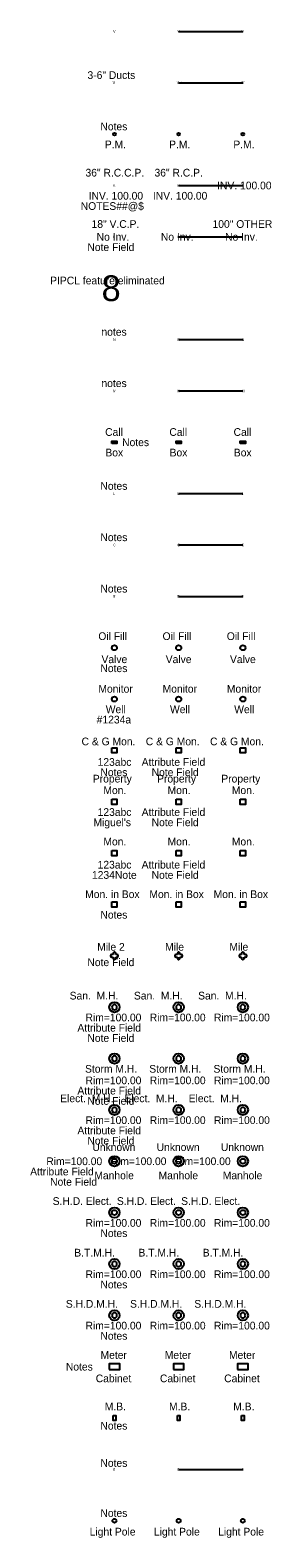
# Model space of a CAD drawing. Extents: x 40011 to 50684, y 49949 to 72236.
# Drawn here: x 49967 to 50061, y 51773 to 52360 of the extents above; entities that cross this region are included whole.
import ezdxf

# ---------------------------------------------------------------- set-up
doc = ezdxf.new("R2010")
doc.units = 0
for name, color, linetype in [('10', 7, 'Continuous'), ('12', 7, 'Continuous'), ('13', 7, 'Continuous'), ('15', 7, 'Continuous'), ('16', 7, 'Continuous'), ('17', 7, 'Continuous'), ('2', 7, 'Continuous'), ('20', 7, 'Continuous'), ('41', 7, 'Continuous'), ('44', 7, 'Continuous'), ('49', 7, 'Continuous'), ('5', 7, 'Continuous'), ('50', 7, 'Continuous'), ('56', 7, 'Continuous'), ('9', 7, 'Continuous')]:
    doc.layers.add(name, color=color, linetype=linetype)

msp = doc.modelspace()

# ---------------------------------------------------------------- linework, layer by layer
at = {"layer": '10'}
for points in [[(50025, 52300), (50050, 52300)], [(50025, 52280), (50050, 52280)]]:
    msp.add_lwpolyline(points, dxfattribs=at)
at = {"layer": '12'}
msp.add_lwpolyline([(50025, 52360), (50050, 52360)], dxfattribs=at)
for centre, radius in [((50000, 51940), 2), ((50025, 51940), 2), ((50050, 51940), 2), ((50000, 51900), 2), ((50000, 51900), 1), ((50025, 51900), 2), ((50025, 51900), 1), ((50050, 51900), 2), ((50050, 51900), 1)]:
    msp.add_circle(centre, radius, dxfattribs=at)
for centre, start, end in [((50000, 51940), 0, 180), ((50000, 51940), 180, 0), ((50025, 51940), 0, 180), ((50025, 51940), 180, 0), ((50050, 51940), 0, 180), ((50050, 51940), 180, 0)]:
    msp.add_arc(centre, 1, start, end, dxfattribs=at)
at = {"layer": '13'}
for centre in [(50000, 51880), (50025, 51880), (50050, 51880)]:
    msp.add_circle(centre, 2, dxfattribs=at)
for centre, start, end in [((50000, 51880), 0, 180), ((50025, 51880), 0, 180), ((50050, 51880), 0, 180), ((50000, 51880), 180, 0), ((50025, 51880), 180, 0), ((50050, 51880), 180, 0)]:
    msp.add_arc(centre, 1, start, end, dxfattribs=at)
at = {"layer": '15'}
for centre in [(50000, 52100), (50025, 52100), (50050, 52100)]:
    msp.add_circle(centre, 1, dxfattribs=at)
at = {"layer": '16'}
for centre in [(50000, 51980), (50025, 51980), (50050, 51980)]:
    msp.add_circle(centre, 2, dxfattribs=at)
for centre, start, end in [((50000, 51980), 0, 180), ((50025, 51980), 0, 180), ((50050, 51980), 0, 180), ((50000, 51980), 180, 0), ((50025, 51980), 180, 0), ((50050, 51980), 180, 0)]:
    msp.add_arc(centre, 1, start, end, dxfattribs=at)
at = {"layer": '17'}
msp.add_lwpolyline([(50025, 52340), (50050, 52340)], dxfattribs=at)
at = {"layer": '2'}
for points in [[(50025, 52240), (50050, 52240)], [(50025, 52220), (50050, 52220)], [(50025, 52180), (50050, 52180)]]:
    msp.add_lwpolyline(points, dxfattribs=at)
at = {"layer": '20'}
for points in [[(49997.95, 51838.95), (50002.05, 51838.95), (50002.05, 51841.05), (49997.95, 51841.05)], [(50022.95, 51838.95), (50027.05, 51838.95), (50027.05, 51841.05), (50022.95, 51841.05)], [(50047.95, 51838.95), (50052.05, 51838.95), (50052.05, 51841.05), (50047.95, 51841.05)]]:
    msp.add_lwpolyline(points, close=True, dxfattribs=at)
at = {"layer": '5'}
for p, q in [((49999.5, 52000.5), (49999, 52000.5)), ((49999, 51999.5), (49999.5, 51999.5)), ((49999.5, 52001), (49999.5, 52000.5)), ((49999.5, 51999.5), (49999.5, 51999)), ((50000.5, 52000.5), (50000.5, 52001)), ((50001, 52000.5), (50000.5, 52000.5)), ((50000.5, 51999), (50000.5, 51999.5)), ((50000.5, 51999.5), (50001, 51999.5)), ((50024.5, 52000.5), (50024, 52000.5)), ((50024, 51999.5), (50024.5, 51999.5)), ((50024.5, 52001), (50024.5, 52000.5)), ((50024.5, 51999.5), (50024.5, 51999)), ((50025.5, 52000.5), (50025.5, 52001)), ((50026, 52000.5), (50025.5, 52000.5)), ((50025.5, 51999), (50025.5, 51999.5)), ((50025.5, 51999.5), (50026, 51999.5)), ((50049.5, 52000.5), (50049, 52000.5)), ((50049, 51999.5), (50049.5, 51999.5)), ((50049.5, 52001), (50049.5, 52000.5)), ((50049.5, 51999.5), (50049.5, 51999)), ((50050.5, 52000.5), (50050.5, 52001)), ((50051, 52000.5), (50050.5, 52000.5)), ((50050.5, 51999), (50050.5, 51999.5)), ((50050.5, 51999.5), (50051, 51999.5))]:
    msp.add_line(p, q, dxfattribs=at)
for points in [[(49999, 52199.5), (49999, 52200.5), (50001, 52200.5), (50001, 52199.5)], [(50024, 52199.5), (50024, 52200.5), (50026, 52200.5), (50026, 52199.5)], [(50049, 52199.5), (50049, 52200.5), (50051, 52200.5), (50051, 52199.5)], [(49999, 52081), (50001, 52081), (50001, 52079), (49999, 52079)], [(50024, 52081), (50026, 52081), (50026, 52079), (50024, 52079)], [(50049, 52081), (50051, 52081), (50051, 52079), (50049, 52079)], [(49999, 52061), (50001, 52061), (50001, 52059), (49999, 52059)], [(50024, 52061), (50026, 52061), (50026, 52059), (50024, 52059)], [(50049, 52061), (50051, 52061), (50051, 52059), (50049, 52059)], [(49999, 52041), (50001, 52041), (50001, 52039), (49999, 52039)], [(50024, 52041), (50026, 52041), (50026, 52039), (50024, 52039)], [(50049, 52041), (50051, 52041), (50051, 52039), (50049, 52039)], [(49999, 52021), (50001, 52021), (50001, 52019), (49999, 52019)], [(50024, 52021), (50026, 52021), (50026, 52019), (50024, 52019)], [(50049, 52021), (50051, 52021), (50051, 52019), (50049, 52019)], [(49999.5, 51821), (50000.5, 51821), (50000.5, 51819), (49999.5, 51819)], [(50024.5, 51821), (50025.5, 51821), (50025.5, 51819), (50024.5, 51819)], [(50049.5, 51821), (50050.5, 51821), (50050.5, 51819), (50049.5, 51819)]]:
    msp.add_lwpolyline(points, close=True, dxfattribs=at)
for points in [[(50025, 52160), (50050, 52160)], [(50025, 52140), (50050, 52140)], [(50025, 51800), (50050, 51800)]]:
    msp.add_lwpolyline(points, dxfattribs=at)
for centre, radius in [((50000, 52320), 0.5), ((50025, 52320), 0.5), ((50050, 52320), 0.5), ((50000, 52120), 1), ((50025, 52120), 1), ((50050, 52120), 1), ((50000, 51780), 0.75), ((50025, 51780), 0.75), ((50050, 51780), 0.75)]:
    msp.add_circle(centre, radius, dxfattribs=at)
for centre, start, end in [((49999, 52000), 90, 270), ((50000, 52001), 0, 180), ((50000, 51999), 180, 0), ((50001, 52000), 270, 90), ((50024, 52000), 90, 270), ((50025, 52001), 0, 180), ((50025, 51999), 180, 0), ((50026, 52000), 270, 90), ((50049, 52000), 90, 270), ((50050, 52001), 0, 180), ((50050, 51999), 180, 0), ((50051, 52000), 270, 90)]:
    msp.add_arc(centre, 0.5, start, end, dxfattribs=at)
at = {"layer": '56'}
for centre, radius in [((50000, 51920), 2), ((50000, 51920), 1), ((50025, 51920), 2), ((50025, 51920), 1), ((50050, 51920), 2), ((50050, 51920), 1)]:
    msp.add_circle(centre, radius, dxfattribs=at)
at = {"layer": '9'}
for centre in [(50000, 51960), (50025, 51960), (50050, 51960), (50000, 51860), (50025, 51860), (50050, 51860)]:
    msp.add_circle(centre, 2, dxfattribs=at)
for centre, start, end in [((50000, 51960), 0, 180), ((50000, 51960), 180, 0), ((50025, 51960), 0, 180), ((50025, 51960), 180, 0), ((50050, 51960), 0, 180), ((50050, 51960), 180, 0), ((50000, 51860), 0, 180), ((50000, 51860), 180, 0), ((50025, 51860), 0, 180), ((50025, 51860), 180, 0), ((50050, 51860), 0, 180), ((50050, 51860), 180, 0)]:
    msp.add_arc(centre, 1, start, end, dxfattribs=at)

# ---------------------------------------------------------------- texts
at = {"layer": '12'}
for s, p in [('Elect.  M.H.', (49978.9, 51943)), ('Elect.  M.H.', (50003.9, 51943)), ('Elect.  M.H.', (50028.9, 51943)), ('S.H.D. Elect.', (49975.96, 51903)), ('S.H.D. Elect.', (50000.96, 51903)), ('S.H.D. Elect.', (50025.96, 51903))]:
    msp.add_text(s, height=3, dxfattribs=at).set_placement(p)
at = {"layer": '13'}
for p in [(49984.37, 51882.9), (50009.37, 51882.9), (50034.37, 51882.9)]:
    msp.add_text('B.T.M.H.', height=3, dxfattribs=at).set_placement(p)
at = {"layer": '15'}
for s, p in [('Monitor', (49993.76, 52102.5)), ('Monitor', (50018.76, 52102.5)), ('Monitor', (50043.76, 52102.5)), ('Well', (49996.63, 52094.5)), ('Well', (50021.63, 52094.5)), ('Well', (50046.63, 52094.5))]:
    msp.add_text(s, height=3, dxfattribs=at).set_placement(p)
at = {"layer": '16'}
for p in [(49982.58, 51983), (50007.58, 51983), (50032.58, 51983)]:
    msp.add_text('San.  M.H.', height=3, dxfattribs=at).set_placement(p)
at = {"layer": '20'}
for s, p in [('Meter', (49994.59, 51843.05)), ('Meter', (50019.59, 51843.05)), ('Meter', (50044.59, 51843.05)), ('Cabinet', (49992.72, 51833.95)), ('Cabinet', (50017.72, 51833.95)), ('Cabinet', (50042.72, 51833.95))]:
    msp.add_text(s, height=3, dxfattribs=at).set_placement(p)
at = {"layer": '41'}
for s, p in [('3-6" Ducts', (49989.51, 52341.5)), ('Notes', (49994.55, 52321.5)), ('36" R.C.C.P.', (49988.74, 52303.5)), ('NOTES##@$', (49986.89, 52290.5)), ('INV. 100.00', (49989.97, 52294.5)), ('18" V.C.P.', (49991.1, 52283.5)), ('100" OTHER', (50038.18, 52283.5)), ('No Inv.', (49993.08, 52278.5)), ('No Inv.', (50018.08, 52278.5)), ('No Inv.', (50043.08, 52278.5)), ('Note Field', (49989.48, 52274.5)), ('notes', (49994.95, 52241.5)), ('notes', (49994.95, 52221.5)), ('Notes', (50003, 52198.5)), ('Notes', (49994.55, 52181.5)), ('Notes', (49994.55, 52161.5)), ('Notes', (49994.55, 52141.5)), ('Notes', (49994.55, 52110.5)), ('#1234a', (49993.1, 52090.5)), ('Notes', (49994.55, 52070)), ('Note Field', (50014.48, 52070)), ('123abc', (49993.46, 52054.5)), ('Attribute Field', (50010.6, 52054.5)), ("Miguel's", (49991.85, 52050.5)), ('Note Field', (50014.48, 52050.5)), ('1234Note', (49991.26, 52030)), ('Note Field', (50014.48, 52030)), ('Mon. in Box', (49988.61, 52022.5)), ('Mon. in Box', (50013.61, 52022.5)), ('Mon. in Box', (50038.61, 52022.5)), ('Notes', (49994.55, 52014.5)), (' Mile 2', (49992.19, 52002)), (' Mile ', (50018.62, 52002)), (' Mile ', (50043.62, 52002)), ('Note Field', (49989.48, 51996)), ('Rim=100.00', (49988.75, 51974.5)), ('Rim=100.00', (50013.75, 51974.5)), ('Rim=100.00', (50038.75, 51974.5)), ('Attribute Field', (49985.6, 51970.5)), ('Note Field', (49989.48, 51966.5)), ('Storm M.H.', (49988.56, 51954.5)), ('Storm M.H.', (50013.56, 51954.5)), ('Storm M.H.', (50038.56, 51954.5)), ('Rim=100.00', (49988.75, 51950)), ('Rim=100.00', (50013.75, 51950)), ('Rim=100.00', (50038.75, 51950)), ('Attribute Field', (49985.6, 51946)), ('Note Field', (49989.48, 51942)), ('Rim=100.00', (49988.75, 51934.5)), ('Rim=100.00', (50013.75, 51934.5)), ('Rim=100.00', (50038.75, 51934.5)), ('Attribute Field', (49985.6, 51930.5)), ('Note Field', (49989.48, 51926.5)), ('Attribute Field', (49967.2, 51914.5)), ('Rim=100.00', (49973.5, 51918.5)), ('Rim=100.00', (49998.5, 51918.5)), ('Rim=100.00', (50023.5, 51918.5)), ('Note Field', (49974.97, 51910.5)), ('Rim=100.00', (49988.75, 51894.5)), ('Notes', (49994.55, 51890.5)), ('Rim=100.00', (50013.75, 51894.5)), ('Rim=100.00', (50038.75, 51894.5)), ('Rim=100.00', (49988.75, 51874.5)), ('Rim=100.00', (50013.75, 51874.5)), ('Rim=100.00', (50038.75, 51874.5)), ('Notes', (49994.55, 51870.5)), ('Rim=100.00', (49988.75, 51854.5)), ('Rim=100.00', (50013.75, 51854.5)), ('Rim=100.00', (50038.75, 51854.5)), ('Notes', (49994.55, 51850.5)), ('Notes', (49981.1, 51838.5)), ('Notes', (49994.55, 51815.5)), ('Notes', (49994.55, 51801)), ('Notes', (49994.55, 51781.5))]:
    msp.add_text(s, height=3, dxfattribs=at).set_placement(p)
for s, p in [('36" R.C.P.', (50015.6, 52303.5)), ('INV. 100.00', (50039.97, 52298.5)), ('INV. 100.00', (50014.97, 52294.5))]:
    msp.add_text(s, height=3, rotation=360, dxfattribs=at).set_placement(p)
at = {"layer": '44'}
for s, height, p in [('Pav. Mark. CTV', 0.2, (49999.08, 52340.3)), ('Overhang', 0.2, (49999.39, 52140.3)), ('Landscape Tie', 0.1, (49999.52, 51800.15))]:
    msp.add_text(s, height=height, dxfattribs=at).set_placement(p)
for s, height, p in [('Pav. Mark. CTV', 0.2, (50024.08, 52340.3)), ('Pav. Mark. CTV', 0.2, (50049.08, 52340.3)), ('K', 1, (49999.5, 52299.5)), ('K', 1, (50024.5, 52299.5)), ('K', 1, (50049.5, 52299.5)), ('I', 1, (49999.5, 52279.5)), ('I', 1, (50024.5, 52279.5)), ('I', 1, (50049.5, 52279.5)), ('N', 1, (49999.5, 52239.5)), ('N', 1, (50024.5, 52239.5)), ('N', 1, (50049.5, 52239.5)), ('M', 1, (49999.5, 52219.5)), ('M', 1, (50024.5, 52219.5)), ('M', 1, (50049.5, 52219.5)), ('L', 1, (49999.5, 52179.5)), ('L', 1, (50024.5, 52179.5)), ('L', 1, (50049.5, 52179.5)), ('C', 1, (49999.5, 52159.5)), ('C', 1, (50024.5, 52159.5)), ('C', 1, (50049.5, 52159.5)), ('8', 1, (49999.5, 52139.5)), ('Overhang', 0.2, (50024.39, 52140.3)), ('8', 1, (50024.5, 52139.5)), ('Overhang', 0.2, (50049.39, 52140.3)), ('8', 1, (50049.5, 52139.5)), ('8', 1, (49999.5, 51799.5)), ('Landscape Tie', 0.1, (50024.52, 51800.15)), ('8', 1, (50024.5, 51799.5)), ('Landscape Tie', 0.1, (50049.52, 51800.15)), ('8', 1, (50049.5, 51799.5))]:
    msp.add_text(s, height=height, rotation=360, dxfattribs=at).set_placement(p)
at = {"layer": '49'}
for s, p in [('V', (49999.5, 52359.5)), ('V', (50024.5, 52359.5)), ('V', (50049.5, 52359.5)), ('8', (49999.5, 52339.5)), ('8', (50024.5, 52339.5)), ('8', (50049.5, 52339.5))]:
    msp.add_text(s, height=1, rotation=360, dxfattribs=at).set_placement(p)
at = {"layer": '5'}
for s, p in [('P.M.', (49996.28, 52314.5)), ('P.M.', (50021.28, 52314.5)), ('P.M.', (50046.28, 52314.5)), ('Call', (49996.38, 52202.5)), ('Call', (50021.38, 52202.5)), ('Call', (50046.38, 52202.5)), ('Box', (49996.48, 52194.5)), ('Box', (50021.48, 52194.5)), ('Box', (50046.48, 52194.5)), ('Oil Fill', (49993.74, 52123)), ('Oil Fill', (50018.74, 52123)), ('Oil Fill', (50043.74, 52123)), ('Valve', (49994.97, 52114)), ('Valve', (50019.97, 52114)), ('Valve', (50044.97, 52114)), ('C & G Mon.', (49987.21, 52082)), ('C & G Mon.', (50012.21, 52082)), ('C & G Mon.', (50037.21, 52082)), ('123abc', (49993.46, 52074)), ('Attribute Field', (50010.6, 52074)), ('Property', (49991.6, 52067.5)), ('Property', (50016.6, 52067.5)), ('Property', (50041.6, 52067.5)), ('Mon.', (49995.7, 52063)), ('Mon.', (50020.7, 52063)), ('Mon.', (50045.7, 52063)), ('123abc', (49993.46, 52034)), ('Attribute Field', (50010.6, 52034)), ('M.B.', (49996.25, 51823)), ('M.B.', (50021.25, 51823)), ('M.B.', (50046.25, 51823)), ('Light Pole', (49990.37, 51774.25)), ('Light Pole', (50015.37, 51774.25)), ('Light Pole', (50040.37, 51774.25))]:
    msp.add_text(s, height=3, dxfattribs=at).set_placement(p)
for p in [(49995.7, 52043), (50020.7, 52043), (50045.7, 52043)]:
    msp.add_text('Mon.', height=3, rotation=360, dxfattribs=at).set_placement(p)
at = {"layer": '50'}
msp.add_text('PIPCL feature eliminated', height=3, dxfattribs=at).set_placement((49974.99, 52261.5))
msp.add_text('8', height=10, rotation=360, dxfattribs=at).set_placement((49995, 52255))
at = {"layer": '56'}
for s, p in [('Unknown', (49991.43, 51924)), ('Unknown', (50016.43, 51924)), ('Unknown', (50041.43, 51924)), ('Manhole', (49992.18, 51913)), ('Manhole', (50017.18, 51913)), ('Manhole', (50042.18, 51913))]:
    msp.add_text(s, height=3, dxfattribs=at).set_placement(p)
at = {"layer": '9'}
for p in [(49981.09, 51862.97), (50006.09, 51862.97), (50031.09, 51862.97)]:
    msp.add_text('S.H.D.M.H.', height=3, dxfattribs=at).set_placement(p)

doc.saveas('drawing.dxf')
